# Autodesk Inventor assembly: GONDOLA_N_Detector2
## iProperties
Shininess: 64.0
Length Units: 11272
Angle Units: 11279
Time Units: 11290
Mass Units: 11286
Length Display Precision: 3
Angle Display Precision: 2
Compacted: True
Part Number: GONDOLA_N_Detector2
Document SubType Name: Weldment
Created: 2004-12
Designer: John Blackburn
Manufacturer: Standard
Standards Organization: Custom
Density: 0.0
Volumn: 0.0
Area: 0.0
PropertySet Name: Model Information
Control State: 0
Master: False
Checked Out: False
Author: John Blackburn
